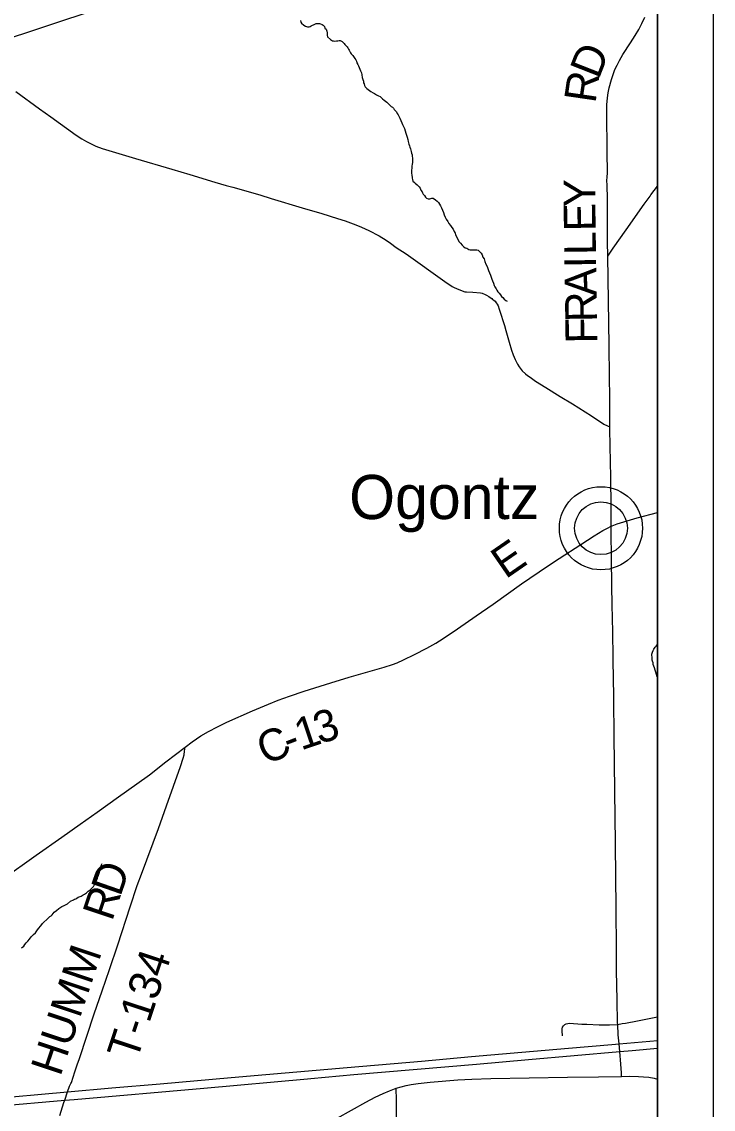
# Model space of a CAD drawing. Extents: x 0 to 34, y 0 to 22.
# Drawn here: x 7.762 to 9, y 14.854 to 16.8 of the extents above; entities that cross this region are included whole.
import ezdxf

# ---------------------------------------------------------------- set-up
doc = ezdxf.new("R2010")
doc.units = 0
for name, color, linetype in [('GM_X_Corporation', 7, 'Continuous'), ('GM_X_County_Road', 7, 'Continuous'), ('GM_X_County_Road_Text', 7, 'Continuous'), ('GM_X_Interstate_Route', 7, 'Continuous'), ('GM_X_Minor_River', 7, 'Continuous'), ('GM_X_Rail_Line', 7, 'Continuous'), ('GM_X_Township_Road', 7, 'Continuous'), ('GM_X_Township_Road_Text', 7, 'Continuous'), ('GM_X_Unincorporated', 7, 'Continuous'), ('GM_X_Unincorporated_Location', 7, 'Continuous'), ('GM_X_Unincorporated_Text', 7, 'Continuous'), ('SH_Data', 7, 'Continuous')]:
    doc.layers.add(name, color=color, linetype=linetype)

msp = doc.modelspace()

# ---------------------------------------------------------------- linework, layer by layer
at = {"layer": 'GM_X_Corporation'}
for points in [[(8.9, 14.1), (8.9, 18.9067)], [(8.9, 14.1), (8.9, 16.8293)]]:
    msp.add_lwpolyline(points, dxfattribs=at)
at = {"layer": 'GM_X_County_Road'}
for points in [[(8.8174, 15.8976), (8.8192, 15.8985), (8.828, 15.9019), (8.8399, 15.9058), (8.8638, 15.9126), (8.9, 15.9221)], [(8.0546, 15.5023), (8.0671, 15.512), (8.0748, 15.5173), (8.0827, 15.5224), (8.0962, 15.5301), (8.1128, 15.5387), (8.1296, 15.5468), (8.1751, 15.5671), (8.2036, 15.5795), (8.221, 15.5863), (8.2415, 15.5937), (8.268, 15.6025), (8.3155, 15.6175), (8.3482, 15.6274), (8.4109, 15.6456), (8.4257, 15.6502), (8.4344, 15.6534), (8.4457, 15.6584), (8.4652, 15.6681), (8.4872, 15.6796), (8.5034, 15.6887), (8.5166, 15.6969), (8.5423, 15.7143), (8.5756, 15.7373), (8.6062, 15.7585), (8.6569, 15.7946), (8.7032, 15.826), (8.7239, 15.8398), (8.7632, 15.8649), (8.7867, 15.8802), (8.8026, 15.8899), (8.8108, 15.8945), (8.8174, 15.8976)], [(7.6366, 15.2062), (7.6558, 15.2169), (7.6715, 15.2268), (7.692, 15.2408), (7.7275, 15.2659), (7.7883, 15.309), (7.8339, 15.3414), (7.8669, 15.3647), (7.8974, 15.3861), (7.9354, 15.4133), (7.9684, 15.4365), (7.991, 15.4529), (8.0202, 15.476), (8.0546, 15.5023)], [(8.4323, 14.892), (8.4411, 14.8947), (8.4502, 14.897), (8.4594, 14.8988), (8.4717, 14.9006), (8.4934, 14.9029), (8.543, 14.907), (8.5679, 14.9083), (8.6021, 14.9094), (8.7389, 14.9115), (8.7947, 14.9125), (8.836, 14.9131)], [(8.836, 14.9131), (8.8505, 14.9133), (8.8661, 14.9131), (8.8754, 14.9126), (8.8848, 14.9116), (8.894, 14.91), (8.9, 14.9085)], [(8.3268, 14.8383), (8.3783, 14.8673), (8.3948, 14.876), (8.4089, 14.8827), (8.4204, 14.8876), (8.4323, 14.892)]]:
    msp.add_lwpolyline(points, dxfattribs=at)
at = {"layer": 'GM_X_Interstate_Route'}
msp.add_line((8.2739, 14.9088), (8.2799, 14.9093), dxfattribs=at)
for points in [[(7.6974, 14.8727), (7.8443, 14.8856), (7.9234, 14.8925), (8.0102, 14.8998), (8.1371, 14.9111), (8.199, 14.9163), (8.3446, 14.9293), (8.4777, 14.9405), (8.5675, 14.9487), (8.6573, 14.9563), (8.7409, 14.9636), (8.8184, 14.9702), (8.8314, 14.9714), (8.9, 14.9774)], [(8.2799, 14.9093), (8.3564, 14.9163), (8.5763, 14.9352), (8.6692, 14.9434), (8.8326, 14.9577), (8.8549, 14.9597), (8.9, 14.9635)], [(7.6338, 14.8533), (7.6358, 14.8534), (7.6388, 14.8536), (7.6607, 14.855), (7.7165, 14.8596), (7.8392, 14.8704), (7.8558, 14.8719), (8.088, 14.8919), (8.2739, 14.9088)]]:
    msp.add_lwpolyline(points, dxfattribs=at)
at = {"layer": 'GM_X_Minor_River'}
for points in [[(8.2612, 16.8029), (8.262, 16.7998), (8.2631, 16.7979), (8.2674, 16.7942), (8.27, 16.7927), (8.2735, 16.7916), (8.2765, 16.7916), (8.2784, 16.792), (8.2803, 16.7932), (8.2826, 16.7943), (8.2845, 16.7951), (8.2867, 16.7963), (8.289, 16.7971), (8.2913, 16.7975), (8.2951, 16.7971), (8.297, 16.7968), (8.2997, 16.7956), (8.3016, 16.7945), (8.3039, 16.7919), (8.305, 16.7892), (8.3074, 16.787), (8.3085, 16.7836), (8.3089, 16.7805)], [(8.3089, 16.7805), (8.309, 16.7763), (8.3098, 16.7733), (8.3148, 16.7688), (8.3182, 16.7665), (8.3201, 16.7662), (8.3228, 16.7658), (8.3258, 16.7662), (8.3281, 16.7663), (8.3304, 16.7667), (8.3323, 16.7671), (8.3357, 16.7648), (8.3395, 16.7618), (8.3407, 16.7599), (8.3426, 16.758), (8.3445, 16.7558), (8.3461, 16.7535), (8.3472, 16.7512), (8.3484, 16.7493), (8.3496, 16.7471), (8.3507, 16.7448), (8.3519, 16.7429), (8.355, 16.7399), (8.3584, 16.7346), (8.36, 16.7323), (8.3615, 16.7301), (8.3623, 16.727), (8.3639, 16.724), (8.365, 16.7217), (8.3662, 16.7187), (8.3674, 16.7157), (8.3685, 16.7123), (8.3701, 16.7089), (8.3709, 16.7054), (8.3717, 16.7005), (8.3729, 16.6971), (8.3737, 16.6941), (8.3741, 16.6914), (8.3749, 16.6891), (8.3756, 16.6861), (8.3772, 16.6842), (8.3799, 16.6808), (8.3868, 16.6755), (8.391, 16.6733), (8.3937, 16.6718), (8.3971, 16.6699), (8.4005, 16.6681), (8.4036, 16.6666), (8.4055, 16.6647), (8.4082, 16.6625), (8.4109, 16.6602), (8.4132, 16.6583), (8.4155, 16.6568), (8.4174, 16.6549), (8.4193, 16.6527), (8.4216, 16.6508), (8.4235, 16.6489), (8.4258, 16.6474), (8.4277, 16.6459), (8.4289, 16.6436), (8.4308, 16.6414), (8.4328, 16.6391), (8.4343, 16.6365), (8.4359, 16.6338), (8.4374, 16.6312), (8.439, 16.6281), (8.4409, 16.624), (8.4425, 16.6198), (8.444, 16.6164), (8.4456, 16.613), (8.4471, 16.6092), (8.4483, 16.605), (8.4499, 16.6009), (8.451, 16.5974), (8.4522, 16.5937), (8.453, 16.5899), (8.4538, 16.5861), (8.455, 16.5815), (8.4562, 16.5781), (8.457, 16.5758), (8.4578, 16.5732), (8.4585, 16.5709), (8.4593, 16.5682), (8.4601, 16.5652), (8.4609, 16.5622), (8.4613, 16.5599), (8.4617, 16.5565), (8.4618, 16.5527), (8.4614, 16.5492), (8.4611, 16.5447), (8.4607, 16.5424), (8.4604, 16.5405), (8.46, 16.5332), (8.4601, 16.5298), (8.4605, 16.5252), (8.4609, 16.5222), (8.4613, 16.5203), (8.4617, 16.518), (8.4625, 16.5154), (8.4644, 16.5135), (8.4663, 16.5116)], [(8.4663, 16.5116), (8.4698, 16.5086), (8.4733, 16.5052), (8.4752, 16.5026), (8.4767, 16.4992), (8.4787, 16.4961), (8.4798, 16.4942), (8.481, 16.492), (8.4829, 16.4893), (8.4848, 16.4863), (8.4868, 16.4848), (8.4898, 16.4837), (8.4929, 16.4837), (8.4963, 16.4845), (8.4986, 16.4845), (8.5028, 16.4815), (8.5058, 16.4793), (8.5081, 16.477), (8.5101, 16.474), (8.512, 16.471), (8.5135, 16.4672), (8.5155, 16.4634), (8.5171, 16.4589), (8.5186, 16.4551), (8.5202, 16.4509), (8.5221, 16.4471), (8.5248, 16.443), (8.5268, 16.4396), (8.5295, 16.4358), (8.5322, 16.432), (8.5345, 16.429), (8.5364, 16.4252), (8.5379, 16.4222), (8.5387, 16.4195), (8.5399, 16.4165), (8.5453, 16.4063), (8.5476, 16.404), (8.5507, 16.4006), (8.553, 16.3984), (8.5561, 16.3961), (8.5587, 16.395), (8.5607, 16.3939), (8.5626, 16.3928), (8.5649, 16.392), (8.5668, 16.392), (8.5687, 16.3921), (8.5717, 16.3921), (8.574, 16.3921), (8.577, 16.3921), (8.5793, 16.3918), (8.5824, 16.3888), (8.5843, 16.3865), (8.5862, 16.3835), (8.5878, 16.3793), (8.5897, 16.3759), (8.5913, 16.3717), (8.5929, 16.3664), (8.5952, 16.3623), (8.5967, 16.3589), (8.5979, 16.3551), (8.5995, 16.3509), (8.601, 16.3471), (8.6022, 16.3433), (8.6038, 16.3399), (8.6049, 16.3369), (8.6065, 16.3327), (8.6081, 16.3285), (8.6092, 16.3259), (8.6112, 16.3225), (8.6127, 16.3202), (8.6146, 16.3172), (8.6166, 16.3145), (8.6189, 16.3119), (8.6212, 16.3085), (8.6231, 16.307), (8.6258, 16.304), (8.6289, 16.3017), (8.6312, 16.3006)], [(8.8923, 15.6534), (8.8915, 15.6561), (8.8908, 15.658), (8.8907, 15.6618), (8.8899, 15.6686), (8.891, 15.6724), (8.8925, 15.6755), (8.8936, 15.6778), (8.8962, 15.6812), (8.8977, 15.6832), (8.8996, 15.6855), (8.9, 15.6859)], [(8.9, 15.6275), (8.8998, 15.628), (8.8986, 15.6322), (8.8974, 15.6364), (8.8963, 15.6401), (8.8947, 15.6443), (8.8935, 15.6473), (8.8927, 15.65), (8.8923, 15.6534)], [(7.762, 15.1431), (7.7658, 15.1465), (7.768, 15.1492), (7.7703, 15.1519), (7.7729, 15.1554), (7.7763, 15.1588), (7.7793, 15.1631), (7.7834, 15.1669), (7.7868, 15.17), (7.7894, 15.1734), (7.7924, 15.1776), (7.7962, 15.1823), (7.7996, 15.1869), (7.8097, 15.1965), (7.8127, 15.1992), (7.8146, 15.2007), (7.8165, 15.2023), (7.8203, 15.2069), (7.8244, 15.2103), (7.8286, 15.2134), (7.8339, 15.2169), (7.838, 15.2192), (7.8418, 15.2208), (7.8441, 15.2219), (7.8497, 15.227), (7.8546, 15.2289), (7.8569, 15.2301), (7.8592, 15.2312), (7.8611, 15.232), (7.863, 15.2336), (7.8683, 15.2359), (7.8724, 15.2378), (7.8743, 15.239), (7.8762, 15.2402), (7.8781, 15.2417), (7.8811, 15.2444), (7.8841, 15.2467), (7.8864, 15.2486), (7.889, 15.251), (7.8905, 15.2529), (7.892, 15.2556), (7.8935, 15.2579), (7.895, 15.2613), (7.8965, 15.2647), (7.898, 15.2678), (7.8987, 15.2701), (7.8994, 15.2731), (7.9005, 15.277), (7.902, 15.2808), (7.9031, 15.2854), (7.9038, 15.2876), (7.9046, 15.2907), (7.9053, 15.293), (7.9061, 15.2941)]]:
    msp.add_lwpolyline(points, dxfattribs=at)
at = {"layer": 'GM_X_Rail_Line'}
msp.add_lwpolyline([(4.7274, 15.7912), (4.9149, 15.8505), (5.235, 15.9568), (5.5432, 16.0566), (5.6906, 16.1019), (6.056, 16.2214), (6.3367, 16.3138), (6.6888, 16.4288), (7.0003, 16.5302), (7.5012, 16.6931), (7.6844, 16.7528), (7.8339, 16.8018), (7.9505, 16.8406), (8.0234, 16.8694), (8.0878, 16.9029), (8.1469, 16.9344), (8.2358, 16.9935), (8.3923, 17.1058), (8.5744, 17.2368), (8.7463, 17.3593), (8.8719, 17.4493), (8.9, 17.4694)], dxfattribs=at)
at = {"layer": 'GM_X_Township_Road'}
for points in [[(8.811, 16.381), (8.8106, 16.4063), (8.8108, 16.4417), (8.8106, 16.4853), (8.81, 16.5061), (8.8098, 16.518), (8.8101, 16.5206), (8.8105, 16.5317), (8.8103, 16.5661), (8.8099, 16.5879), (8.8098, 16.6176), (8.8094, 16.6424), (8.8096, 16.6518), (8.8106, 16.6642), (8.8119, 16.6733), (8.8138, 16.6823), (8.8178, 16.6972), (8.8206, 16.7061), (8.824, 16.7147), (8.8278, 16.723), (8.8321, 16.7311), (8.8384, 16.7418), (8.852, 16.7627), (8.8604, 16.7757), (8.8667, 16.7864), (8.8723, 16.7974), (8.8773, 16.8086)], [(7.7514, 16.6757), (7.794, 16.6445), (7.8144, 16.6303), (7.8598, 16.5975), (7.87, 16.5907), (7.878, 16.5859), (7.8863, 16.5817), (7.8948, 16.578), (7.9063, 16.5736), (7.9121, 16.5717), (7.9658, 16.5558), (8.0307, 16.5365), (8.063, 16.5268), (8.1076, 16.5132), (8.1283, 16.5072), (8.1402, 16.5043), (8.1883, 16.4906), (8.2089, 16.4842), (8.2644, 16.4677), (8.2994, 16.4574), (8.3276, 16.4485), (8.3413, 16.4442), (8.3604, 16.4368), (8.3703, 16.4328), (8.3832, 16.4269), (8.4019, 16.4173), (8.4148, 16.4096), (8.4225, 16.4041), (8.4325, 16.3967), (8.4501, 16.385), (8.5198, 16.3358), (8.5324, 16.3269), (8.5351, 16.3253), (8.5416, 16.3222), (8.5554, 16.3174), (8.5586, 16.3169), (8.5698, 16.3163), (8.5831, 16.3151), (8.5861, 16.3145), (8.5917, 16.3124), (8.5942, 16.3111), (8.5983, 16.3085), (8.6007, 16.3071), (8.6034, 16.3052), (8.605, 16.3037), (8.6071, 16.3024), (8.6095, 16.3002), (8.6114, 16.2976), (8.6132, 16.2949), (8.6147, 16.292), (8.6169, 16.2864), (8.6175, 16.2845)], [(8.811, 16.381), (8.821, 16.395), (8.8444, 16.428), (8.8764, 16.4738), (8.8869, 16.4884), (8.8883, 16.491), (8.9, 16.5065)], [(8.8147, 16.0758), (8.8148, 16.1283), (8.8144, 16.1652), (8.8138, 16.2212), (8.811, 16.381)], [(8.6175, 16.2845), (8.6262, 16.2569), (8.6289, 16.248), (8.6346, 16.2272), (8.639, 16.2127), (8.642, 16.2042), (8.6455, 16.196), (8.6496, 16.1879), (8.6526, 16.1828), (8.658, 16.1758), (8.664, 16.1701), (8.6677, 16.1675), (8.6723, 16.1642), (8.6821, 16.1572), (8.7001, 16.1457), (8.7257, 16.1301)], [(8.7257, 16.1301), (8.7479, 16.1166), (8.7821, 16.0951), (8.8039, 16.0803), (8.8105, 16.0775), (8.8147, 16.0758)], [(8.8174, 15.8976), (8.817, 15.9311), (8.8164, 15.9869), (8.8159, 16.0118), (8.8156, 16.0429), (8.8147, 16.0703), (8.8147, 16.0758)], [(8.829, 15.0063), (8.8288, 15.0093), (8.8278, 15.0496), (8.8271, 15.1025), (8.8269, 15.1367), (8.8261, 15.2175), (8.8254, 15.2673), (8.8248, 15.3326), (8.8243, 15.3761), (8.8228, 15.5222), (8.822, 15.5875), (8.8214, 15.631), (8.821, 15.6518), (8.8208, 15.6608), (8.8205, 15.7099), (8.8196, 15.7311), (8.8193, 15.7587), (8.8186, 15.7894), (8.8181, 15.8421), (8.8175, 15.8855), (8.8174, 15.8976)], [(7.8302, 14.843), (7.8378, 14.8664), (7.8392, 14.8704), (7.8443, 14.8856), (7.8477, 14.8955), (7.8498, 14.9006), (7.8512, 14.9021), (7.8575, 14.9211), (7.8613, 14.9336), (7.8655, 14.9454), (7.8921, 15.0249), (7.9061, 15.0661), (7.919, 15.1044), (7.934, 15.1485), (7.9563, 15.2164), (7.969, 15.2547), (7.9764, 15.2751), (8.0067, 15.3567), (8.0213, 15.3976), (8.0341, 15.4327), (8.0464, 15.4679), (8.0513, 15.4827), (8.0528, 15.4888), (8.0536, 15.495), (8.0546, 15.5023)], [(8.7301, 14.9855), (8.7295, 14.9949), (8.7296, 14.998), (8.7304, 15.001), (8.7319, 15.0037), (8.7341, 15.0059), (8.7368, 15.0074), (8.7398, 15.0081), (8.7429, 15.0083), (8.7647, 15.0069), (8.774, 15.0066), (8.7957, 15.0056), (8.8143, 15.0053), (8.829, 15.0063)], [(8.829, 15.0063), (8.837, 15.0076), (8.8431, 15.0086), (8.8645, 15.0127), (8.9, 15.02)], [(8.836, 14.9131), (8.8356, 14.9194), (8.8346, 14.9348), (8.8326, 14.9577), (8.8314, 14.9714), (8.83, 14.9875), (8.829, 15.0063)], [(8.448, 14.1), (8.4462, 14.169), (8.4465, 14.1965), (8.4461, 14.2109), (8.4443, 14.2449), (8.4439, 14.2483), (8.4435, 14.2606), (8.4432, 14.2787), (8.4427, 14.296), (8.4414, 14.3766), (8.4374, 14.5972), (8.4362, 14.6563), (8.4344, 14.7588), (8.4333, 14.8084), (8.4331, 14.855), (8.4328, 14.8767), (8.4325, 14.886), (8.4323, 14.892)]]:
    msp.add_lwpolyline(points, dxfattribs=at)
at = {"layer": 'GM_X_Unincorporated'}
for radius in [0.0744, 0.0472]:
    msp.add_circle((8.799, 15.894), radius, dxfattribs=at)
at = {"layer": 'GM_X_Unincorporated_Location'}
msp.add_line((8.799, 15.894), (8.799, 15.894), dxfattribs=at)
at = {"layer": 'SH_Data'}
for p, q in [((9, 21), (9, 14)), ((8.9, 20.9), (8.9, 14.1))]:
    msp.add_line(p, q, dxfattribs=at)

# ---------------------------------------------------------------- texts
at = {"layer": 'GM_X_County_Road_Text'}
for s, rotation, p in [('E', 34.6233, (8.6283, 15.8023)), ('3', 17.7939, (8.295, 15.5073)), ('1', 18.5822, (8.262, 15.4962)), ('C', 23.6104, (8.1987, 15.4696)), ('-', 20.9288, (8.2408, 15.488))]:
    msp.add_text(s, height=0.0568, rotation=rotation, dxfattribs=at).set_placement(p)
at = {"layer": 'GM_X_Township_Road_Text'}
for s, height, rotation, p in [('D', 0.0568, 68.5179, (8.7949, 16.6962)), ('R', 0.0568, 81.677, (8.789, 16.6534)), ('Y', 0.0568, 89.8543, (8.7889, 16.468)), ('E', 0.0568, 90.8357, (8.7896, 16.4258)), ('L', 0.0568, 90.8443, (8.7902, 16.3833)), ('I', 0.0568, 90.8495, (8.7905, 16.36)), ('A', 0.0568, 90.8486, (8.7913, 16.31)), ('R', 0.0568, 90.8476, (8.792, 16.2633)), ('F', 0.0568, 90.8458, (8.7925, 16.225)), ('D', 0.0568, 70.7598, (7.9385, 15.2333)), ('R', 0.0568, 71.5373, (7.9238, 15.1893)), ('HUMM', 0.05682, 71.4973, (7.8312, 14.9116)), ('T-134', 0.05682, 71.7424, (7.9679, 14.939))]:
    msp.add_text(s, height=height, rotation=rotation, dxfattribs=at).set_placement(p)
at = {"layer": 'GM_X_Unincorporated_Text'}
msp.add_text('Ogontz', height=0.07898, rotation=0, dxfattribs=at).set_placement((8.3483, 15.9105))

doc.saveas('drawing.dxf')
